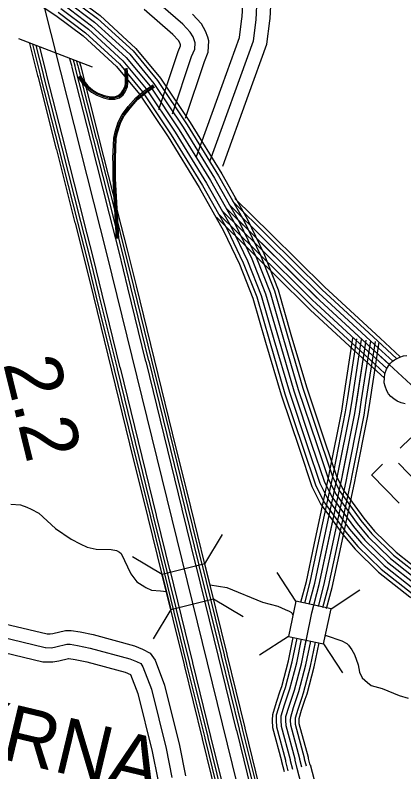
# Model space of a CAD drawing. Extents: x 1551132 to 1791609, y 378168 to 563823.
# Drawn here: x 1701091 to 1703654, y 427562 to 432556 of the extents above; entities that cross this region are included whole.
import ezdxf

# ---------------------------------------------------------------- set-up
doc = ezdxf.new("R2010")
doc.units = 0
for name, color, linetype in [('DESIGN - ROW - Right-of-Way and Easement Labels', 7, 'Continuous'), ('DESIGN - TRAFFIC CONTROL PERMANENT - Signalization', 7, 'Continuous'), ('DESIGN - TRANSPORTATION - Text', 7, 'Continuous'), ('DESIGN - UTILITIES - Cable (Underground) with Text', 7, 'Continuous'), ('SURVEY - CENTERLINE - Preliminary', 7, 'Continuous'), ('SURVEY - CENTERLINE - Preliminary Text', 7, 'Continuous'), ('SURVEY - DRAINAGE - Storm Sewer', 7, 'Continuous'), ('SURVEY - NON-TRANSPORTATION - Features Text', 7, 'Continuous'), ('SURVEY - PROPERTY - Owners', 7, 'Continuous'), ('SURVEY - TRANSPORTATION - Roads', 7, 'Continuous'), ('SURVEY - VEGETATION - Features with Text', 7, 'Continuous')]:
    doc.layers.add(name, color=color, linetype=linetype)

msp = doc.modelspace()

# ---------------------------------------------------------------- linework, layer by layer
at = {"layer": 'DESIGN - TRANSPORTATION - Text'}
for points in [[(1701061.398, 429329.616), (1701125.346, 429324.849), (1701167.17, 429308.332), (1701197.036, 429295.965), (1701246.743, 429269.348), (1701357.632, 429167.92), (1701460.872, 429098.619), (1701520.52, 429065.868), (1701566.294, 429045.301), (1701624.134, 429030.6), (1701724.14, 429029.417), (1701760.073, 429022.983), (1701777.956, 429012.758), (1701788.806, 429002.391)], [(1701788.806, 429002.391), (1701853.504, 428869.054), (1701892.645, 428815.361), (1701945.11, 428782.786), (1701952.11, 428777.994), (1701989.934, 428761.527), (1702049.891, 428756.81), (1702088.582, 428751.293)], [(1702376.4, 428795.261), (1702487.581, 428779.561), (1702722.384, 428681.183), (1702824.115, 428655.949), (1702871.872, 428633.357), (1702897.754, 428623.04), (1702913.646, 428612.84), (1702921.546, 428595.531)], [(1703136.815, 428462.853), (1703141.999, 428461.961), (1703245.613, 428426.693), (1703277.412, 428408.293), (1703289.303, 428398.143), (1703310.97, 428367.85), (1703328.611, 428335.608), (1703353.86, 428267.231), (1703361.318, 428219.088), (1703378.918, 428182.837), (1703414.584, 428152.378), (1703438.367, 428132.078), (1703510.165, 428113.202), (1703623.646, 428065.801), (1703681.469, 428049.1)]]:
    msp.add_lwpolyline(points, dxfattribs=at)
at = {"layer": 'DESIGN - UTILITIES - Cable (Underground) with Text'}
for p, q in [((1703700.78, 429767.058), (1703629.062, 429697.797)), ((1703513.294, 429591.71), (1703442.06, 429522.758)), ((1703441.618, 429522.366), (1703622.858, 429334.705))]:
    msp.add_line(p, q, dxfattribs=at)
msp.add_lwpolyline([(1703618.588, 429599.503), (1704009.76, 429194.514)], dxfattribs=at)
at = {"layer": 'SURVEY - CENTERLINE - Preliminary'}
for points in [[(1702996.559, 425884.268), (1702722.208, 426804.642), (1701697.609, 430973.251), (1701390.958, 432180.974), (1701199.605, 432943.303), (1700793.573, 434580.279), (1700461.64, 435904.33), (1700141.398, 437178.23), (1699727.417, 438823.273), (1699438.174, 439932.735), (1699182.397, 440953.853), (1698979.494, 441790.367), (1698870.455, 442275.771), (1698814.507, 442495.627)], [(1701240.928, 432156.549), (1701187.563, 432369.146)], [(1701257.903, 432160.807), (1701207.137, 432363.037)], [(1701277.302, 432165.674), (1701229.787, 432354.962)], [(1701296.744, 432171.499), (1701253.186, 432345.037)], [(1701465.923, 432213.967), (1701452.282, 432268.327)], [(1701485.598, 432218.909), (1701475.506, 432259.101)], [(1701589.12, 431728.663), (1701469.248, 432200.742), (1701466.148, 432213.084)], [(1701608.778, 431733.654), (1701488.914, 432205.708), (1701485.823, 432218.025)], [(1701504.997, 432223.776), (1701498.072, 432251.36)], [(1701628.161, 431738.58), (1701508.305, 432210.6), (1701505.222, 432222.892)], [(1701521.972, 432228.034), (1701518.272, 432242.768)], [(1701645.127, 431742.888), (1701525.272, 432214.884), (1701522.197, 432227.151)], [(1701364.267, 431670.628), (1701244.111, 432143.865), (1701241.162, 432155.607)], [(1701381.225, 431674.936), (1701261.078, 432148.157), (1701258.128, 432159.874)], [(1701400.616, 431679.853), (1701280.469, 432153.057), (1701277.527, 432164.749)], [(1701420.057, 431685.728), (1701300.127, 432158.04), (1701296.969, 432170.616)], [(1701712.392, 431243.142), (1701589.337, 431727.779)], [(1701732.05, 431248.133), (1701608.994, 431732.771)], [(1701751.433, 431253.059), (1701628.377, 431737.696)], [(1701768.399, 431257.359), (1701645.344, 431741.996)], [(1701487.547, 431185.115), (1701364.492, 431669.744)], [(1701504.513, 431189.415), (1701381.458, 431674.044)], [(1701523.896, 431194.34), (1701400.841, 431678.97)], [(1701543.329, 431200.207), (1701420.274, 431684.845)], [(1701890.129, 430770.371), (1701832.006, 431006.835), (1701768.624, 431256.484)], [(1701834.014, 430756.579), (1701775.948, 430992.827), (1701712.617, 431242.267)], [(1701853.713, 430761.421), (1701795.631, 430997.744), (1701732.275, 431247.258)], [(1701873.129, 430766.196), (1701815.031, 431002.594), (1701751.657, 431252.175)], [(1701608.727, 430700.269), (1701550.662, 430936.534), (1701487.772, 431184.232)], [(1701625.727, 430704.444), (1701567.637, 430940.775), (1701504.73, 431188.54)], [(1701645.143, 430709.219), (1701587.045, 430945.625), (1701524.121, 431193.457)], [(1701664.626, 430714.944), (1701606.719, 430950.542), (1701543.554, 431199.332)], [(1701953.577, 430270.141), (1701834.23, 430755.696)], [(1701973.277, 430274.983), (1701853.93, 430760.537)], [(1701992.693, 430279.758), (1701873.346, 430765.313)], [(1702009.684, 430283.933), (1701890.337, 430769.488)], [(1701764.707, 430222.782), (1701645.36, 430708.344)], [(1701784.19, 430228.507), (1701664.843, 430714.061)], [(1701728.291, 430213.823), (1701608.944, 430699.386)], [(1701745.291, 430218.006), (1701625.944, 430703.569)], [(1702073.141, 429783.695), (1701953.794, 430269.258)], [(1702092.841, 429788.537), (1701973.494, 430274.1)], [(1702112.257, 429793.312), (1701992.91, 430278.875)], [(1702129.248, 429797.487), (1702009.901, 430283.05)], [(1701847.855, 429727.377), (1701728.508, 430212.94)], [(1701864.854, 429731.56), (1701745.507, 430217.123)], [(1701884.27, 429736.336), (1701764.923, 430221.898)], [(1701903.753, 429742.061), (1701784.406, 430227.623)], [(1702192.705, 429297.257), (1702073.358, 429782.812)], [(1702212.404, 429302.099), (1702093.057, 429787.654)], [(1702231.82, 429306.874), (1702112.473, 429792.429)], [(1702248.812, 429311.05), (1702129.465, 429796.604)], [(1701967.418, 429240.939), (1701848.071, 429726.502)], [(1701984.418, 429245.123), (1701865.071, 429730.685)], [(1702003.834, 429249.898), (1701884.487, 429735.461)], [(1702023.317, 429255.623), (1701903.97, 429741.177)], [(1702324.451, 428929.99), (1702232.037, 429305.991)], [(1702341.743, 428932.948), (1702249.028, 429310.166)], [(1702285.369, 428920.239), (1702192.921, 429296.374)], [(1702305.052, 428925.156), (1702212.621, 429301.216)], [(1702060.049, 428864.054), (1701967.635, 429240.056)], [(1702077.04, 428868.288), (1701984.634, 429244.239)], [(1702154.597, 428636.515), (1702004.051, 429249.014)], [(1702116.123, 428878.021), (1702023.534, 429254.74)], [(1702431.824, 428324.374), (1702284.269, 428924.698)], [(1702451.523, 428329.216), (1702305.277, 428924.231)], [(1702470.939, 428333.991), (1702323.351, 428934.481)], [(1702487.939, 428338.166), (1702340.534, 428937.915)], [(1702206.537, 428268.064), (1702058.433, 428870.663)], [(1702223.537, 428272.239), (1702075.016, 428876.546)], [(1702262.436, 428282.739), (1702112.081, 428894.505)], [(1702242.953, 428277.014), (1702153.089, 428642.665)], [(1702551.387, 427837.928), (1702432.04, 428323.49)], [(1702571.087, 427842.77), (1702451.74, 428328.332)], [(1702590.503, 427847.545), (1702471.156, 428333.107)], [(1702607.494, 427851.72), (1702488.147, 428337.282)], [(1702326.101, 427781.609), (1702206.754, 428267.172)], [(1702343.1, 427785.793), (1702223.753, 428271.356)], [(1702362.517, 427790.568), (1702243.17, 428276.131)], [(1702381.999, 427796.293), (1702262.653, 428281.856)], [(1702670.951, 427351.49), (1702551.604, 427837.044)], [(1702690.65, 427356.332), (1702571.303, 427841.886)], [(1702710.067, 427361.107), (1702590.72, 427846.661)], [(1702727.058, 427365.282), (1702607.711, 427850.836)], [(1702445.664, 427295.172), (1702326.317, 427780.734)], [(1702462.664, 427299.355), (1702343.317, 427784.918)], [(1702482.08, 427304.13), (1702362.733, 427789.693)], [(1702501.563, 427309.856), (1702382.216, 427795.41)]]:
    msp.add_lwpolyline(points, dxfattribs=at)
at = {"layer": 'SURVEY - CENTERLINE - Preliminary Text'}
for points in [[(1701209.763, 432652.228), (1701359.142, 432553.751), (1701538.755, 432418.539), (1701759.974, 432215.675), (1701910.154, 432034.471), (1702098.975, 431751.98), (1702303.228, 431418.996), (1702465.316, 431131.347), (1702571.305, 430911.817), (1702659.186, 430687.844), (1702742.334, 430398.612), (1702844.765, 430049.611), (1702965.145, 429690.66), (1703047.685, 429445.92), (1703104.967, 429331.659), (1703251.713, 429128.287), (1703332.061, 429031.801), (1703487.766, 428880.23), (1703693.511, 428717.901), (1704065.744, 428504.096), (1704501.958, 428251.081), (1705242.932, 427815.937), (1705944.374, 427394.851), (1706600.392, 427005.216)], [(1701445.449, 432676.179), (1701634.594, 432533.792), (1701868.705, 432319.103), (1702030.343, 432124.082), (1702225.063, 431832.757), (1702432.292, 431494.924), (1702598.071, 431200.716), (1702708.602, 430971.802), (1702801.124, 430735.979), (1702886.106, 430440.379), (1702987.611, 430094.512), (1703107.05, 429738.394), (1703186.206, 429503.68), (1703233.414, 429409.519), (1703370.077, 429220.106), (1703442.092, 429133.629), (1703586.613, 428992.95), (1703777.609, 428842.255), (1704140.584, 428633.766), (1704577.423, 428380.393), (1705319.364, 427944.673), (1706021.122, 427523.404), (1706676.84, 427133.944)], [(1701459.698, 432696.388), (1701650.41, 432552.818), (1701886.663, 432336.179), (1702050.184, 432138.874), (1702245.88, 431846.091), (1702453.599, 431507.457), (1702619.995, 431212.166), (1702731.268, 430981.702), (1702824.557, 430743.921), (1702909.838, 430447.271), (1703011.194, 430101.929), (1703130.474, 429746.27), (1703209.073, 429513.214), (1703254.621, 429422.37), (1703389.618, 429235.265), (1703460.258, 429150.438), (1703602.93, 429011.559), (1703791.492, 428862.788), (1704152.942, 428655.175), (1704589.881, 428401.735), (1705331.989, 427965.932), (1706033.797, 427544.63), (1706689.465, 427155.195)], [(1701409.708, 432625.478), (1701594.903, 432486.066), (1701823.681, 432276.269), (1701980.569, 432086.972), (1702172.848, 431799.306), (1702378.843, 431463.481), (1702543.097, 431171.99), (1702651.745, 430946.959), (1702742.342, 430716.045), (1702826.565, 430423.079), (1702928.454, 430075.92), (1703048.285, 429718.627), (1703128.841, 429479.763), (1703180.223, 429377.277), (1703321.061, 429182.08), (1703396.526, 429091.461), (1703545.681, 428946.274), (1703742.785, 428790.762), (1704109.593, 428580.065), (1704546.174, 428326.841), (1705287.715, 427891.364), (1705989.34, 427470.17), (1706645.183, 427080.635)], [(1701409.708, 432625.478), (1701594.903, 432486.066), (1701823.681, 432276.269), (1701980.569, 432086.972), (1702172.848, 431799.306), (1702378.843, 431463.481), (1702543.097, 431171.99), (1702651.745, 430946.959), (1702742.342, 430716.045), (1702826.565, 430423.079), (1702928.454, 430075.92), (1703048.285, 429718.627), (1703128.841, 429479.763), (1703180.223, 429377.277), (1703321.061, 429182.08), (1703396.526, 429091.461), (1703545.681, 428946.274), (1703742.785, 428790.762), (1704109.593, 428580.065), (1704546.174, 428326.841), (1705287.715, 427891.364), (1705989.34, 427470.17), (1706645.183, 427080.635)], [(1701427.574, 432650.828), (1701614.745, 432509.933), (1701846.197, 432297.686), (1702005.452, 432105.523), (1702198.956, 431816.032), (1702405.567, 431479.198), (1702570.588, 431186.357), (1702680.169, 430959.376), (1702771.733, 430726.012), (1702856.331, 430431.729), (1702958.029, 430085.22), (1703077.667, 429728.511), (1703157.524, 429491.721), (1703206.823, 429393.394), (1703345.569, 429201.089), (1703419.309, 429112.545), (1703566.147, 428969.616), (1703760.201, 428816.512), (1704125.092, 428606.915), (1704561.799, 428353.617), (1705303.539, 427918.023), (1706005.231, 427496.787), (1706661.016, 427107.285)], [(1701373.967, 432574.776), (1701555.213, 432438.34), (1701778.657, 432233.434), (1701930.795, 432049.863), (1702120.632, 431765.856), (1702325.394, 431432.039), (1702488.124, 431143.264), (1702594.888, 430922.117), (1702683.56, 430696.111), (1702767.025, 430405.778), (1702869.297, 430057.328), (1702989.519, 429698.86), (1703071.476, 429455.845), (1703127.033, 429345.034), (1703272.046, 429144.054), (1703350.961, 429049.293), (1703504.749, 428899.598), (1703707.961, 428739.269), (1704078.602, 428526.363), (1704514.925, 428273.29), (1705256.065, 427838.054), (1705957.557, 427416.935), (1706613.525, 427027.325)], [(1701391.842, 432600.127), (1701575.062, 432462.199), (1701801.165, 432254.852), (1701955.686, 432068.422), (1702146.74, 431782.581), (1702352.119, 431447.764), (1702515.606, 431157.623), (1702623.32, 430934.542), (1702712.951, 430706.078), (1702796.799, 430414.429), (1702898.88, 430066.62), (1703018.902, 429708.744), (1703100.158, 429467.804), (1703153.624, 429361.16), (1703296.554, 429163.071), (1703373.743, 429070.377), (1703525.215, 428922.932), (1703725.368, 428765.011), (1704094.093, 428553.214), (1704530.549, 428300.066), (1705271.89, 427864.705), (1705973.448, 427443.552), (1706629.35, 427053.984)]]:
    msp.add_lwpolyline(points, dxfattribs=at)
at = {"layer": 'SURVEY - DRAINAGE - Storm Sewer'}
for p, q in [((1701600.878, 432211.675), (1701114.881, 432398.205)), ((1702341.384, 428934.215), (1702458.382, 429128.903)), ((1702059.924, 428864.021), (1701865.245, 428981.007)), ((1702941.814, 428687.986), (1702818.101, 428878.475)), ((1703174.224, 428638.592), (1703364.713, 428762.305)), ((1702398.808, 428703.95), (1702593.495, 428586.981)), ((1702117.348, 428633.757), (1702000.375, 428439.06)), ((1702892.42, 428455.576), (1702701.939, 428331.879)), ((1703124.78, 428406.19), (1703248.476, 428215.718))]:
    msp.add_line(p, q, dxfattribs=at)
for points in [[(1702117.348, 428633.757), (1702398.808, 428703.95), (1702341.384, 428934.215), (1702059.924, 428864.021)], [(1702892.42, 428455.576), (1703124.83, 428406.182), (1703174.224, 428638.592), (1702941.814, 428687.986)]]:
    msp.add_lwpolyline(points, close=True, dxfattribs=at)
at = {"layer": 'SURVEY - NON-TRANSPORTATION - Features Text'}
for points in [[(1701505.714, 432148.915), (1701521.047, 432122.981), (1701559.779, 432077.505), (1701594.745, 432048.304), (1701629.894, 432027.295), (1701673.068, 432010.503), (1701708.576, 432001.895), (1701747.791, 432001.203), (1701778.091, 432010.362), (1701802.623, 432030.196), (1701815.931, 432049.921), (1701831.031, 432083.889), (1701833.356, 432105.756), (1701833.531, 432134.24), (1701833.614, 432148.615), (1701829.581, 432204.684)], [(1701513.463, 432153.499), (1701528.396, 432128.231), (1701566.137, 432083.922), (1701599.97, 432055.663), (1701633.861, 432035.412), (1701675.768, 432019.112), (1701709.725, 432010.878), (1701746.541, 432010.228), (1701773.799, 432018.47), (1701795.915, 432036.346), (1701808.032, 432054.296), (1701822.231, 432086.247), (1701824.356, 432106.264), (1701824.531, 432134.298), (1701824.615, 432148.315), (1701820.606, 432204.042)], [(1701519.488, 432157.057), (1701534.113, 432132.315), (1701571.079, 432088.914), (1701604.036, 432061.388), (1701636.944, 432041.721), (1701677.868, 432025.804), (1701710.625, 432017.862), (1701745.566, 432017.245), (1701770.466, 432024.779), (1701790.699, 432041.129), (1701801.882, 432057.705), (1701815.39, 432088.08), (1701817.356, 432106.656), (1701817.531, 432134.34), (1701817.615, 432148.082), (1701813.623, 432203.542)], [(1701767.19, 431082.321), (1701746.074, 431475.131), (1701744.908, 431609.335), (1701750.341, 431742.696), (1701757.983, 431783.489), (1701778.374, 431845.449), (1701804.69, 431895.342), (1701843.022, 431947.168), (1701893.38, 432002.92), (1701949.695, 432050.613), (1702005.152, 432088.997)], [(1701915.179, 432033.179), (1701944.212, 432057.763), (1702000.027, 432096.397)], [(1701925.52, 432020.97), (1701953.961, 432045.054), (1702009.135, 432083.239)], [(1701736.15, 431581.659), (1701735.908, 431609.476), (1701741.375, 431743.713), (1701749.249, 431785.731), (1701770.057, 431848.983), (1701797.048, 431900.142), (1701836.048, 431952.877), (1701887.105, 432009.403), (1701915.196, 432033.187)], [(1701752.149, 431581.792), (1701751.908, 431609.226), (1701757.316, 431741.905), (1701764.774, 431781.739), (1701784.84, 431842.699), (1701810.631, 431891.609), (1701848.447, 431942.727), (1701898.263, 431997.878), (1701925.537, 432020.979)], [(1701758.207, 431081.837), (1701737.075, 431474.848), (1701736.15, 431581.676)], [(1701774.182, 431082.696), (1701753.074, 431475.348), (1701752.149, 431581.809)]]:
    msp.add_lwpolyline(points, dxfattribs=at)
at = {"layer": 'SURVEY - PROPERTY - Owners'}
for points in [[(1702128.207, 431903.751), (1702254.138, 432281.919), (1702274.696, 432331.729), (1702277.171, 432373.747), (1702263.596, 432411.956), (1702245.955, 432444.207), (1702196.539, 432496.858), (1702002.402, 432665.379), (1701903.263, 432742.656), (1701812.157, 432823.85), (1701776.633, 432866.318), (1701753.058, 432904.652), (1701731.434, 432938.944), (1701715.867, 432977.179), (1701694.968, 433075.54), (1701612.712, 433410.915), (1701407.575, 434204.294), (1701114.416, 435353.141), (1700809.474, 436522.155), (1700675.51, 437062.385), (1700654.344, 437136.729), (1700646.819, 437178.863), (1700706.402, 437676.726)], [(1702286.512, 431621.818), (1702456.408, 432092.073), (1702570.422, 432407.656), (1702586.264, 432533.851), (1702586.772, 432543.376), (1702593.672, 432672.563)], [(1702375.193, 431589.776), (1702662.67, 432385.489), (1702680.236, 432525.442), (1702687.828, 432667.513)], [(1702460.499, 431558.95), (1702630.396, 432029.204), (1702751.41, 432364.163), (1702770.643, 432517.35), (1702771.501, 432533.484), (1702778.401, 432662.654)], [(1702038.751, 431933.543), (1702165.723, 432314.845), (1702181.498, 432353.071), (1702181.923, 432360.196), (1702177.265, 432373.305), (1702168.99, 432388.422), (1702131.091, 432428.806), (1701942.479, 432592.535)], [(1702214.264, 431875.092), (1702339.194, 432250.243), (1702364.352, 432311.195), (1702368.802, 432386.814), (1702360.81, 432409.264), (1702346.652, 432449.14), (1702319.995, 432497.866), (1702259.505, 432562.318)], [(1700937.375, 428559.513), (1701301.017, 428472.469), (1701321.883, 428472.327), (1701339.774, 428475.869), (1701421.981, 428495.294), (1701460.971, 428495.011), (1701519.553, 428485.086), (1701605.443, 428467.469), (1701877.012, 428394.742), (1701929.66, 428372.616), (1701980.992, 428346.299), (1702013.9, 428298.323), (1702076.348, 428134.452), (1702174.663, 427735.975), (1702214.495, 427535.786)], [(1700913.951, 428471.844), (1701289.242, 428382.016), (1701291.075, 428381.825), (1701330.466, 428381.558), (1701359.015, 428387.208), (1701432.23, 428404.509), (1701453.013, 428404.359), (1701502.862, 428395.909), (1701584.585, 428379.15), (1701847.571, 428308.723), (1701891.345, 428290.323), (1701919.177, 428276.056), (1701932.985, 428255.922), (1701989.617, 428107.335), (1702086.106, 427716.249), (1702124.397, 427523.803)], [(1700889.601, 428380.716), (1701273.301, 428288.872), (1701285.842, 428287.564), (1701339.391, 428287.197), (1701379.015, 428295.048), (1701442.88, 428310.131), (1701444.738, 428310.123), (1701485.504, 428303.214), (1701562.902, 428287.339), (1701816.963, 428219.304), (1701851.512, 428204.779), (1701851.587, 428204.745), (1701899.453, 428079.142), (1701994.05, 427695.74), (1702030.741, 427511.344)], [(1703355.168, 426211.044), (1703154.273, 426799.859), (1702951.544, 427584.771)], [(1703441.016, 426240.336), (1703279.561, 426713.557), (1703241.237, 426825.885), (1703147.598, 427188.403), (1703039.367, 427607.455)]]:
    msp.add_lwpolyline(points, dxfattribs=at)
at = {"layer": 'SURVEY - TRANSPORTATION - Roads'}
for points in [[(1702738.168, 431073.038), (1702501.332, 431306.819)], [(1702759.942, 431095.097), (1702523.106, 431328.878)], [(1702777.308, 431112.689), (1702540.472, 431346.47)], [(1702694.619, 431028.903), (1702457.783, 431262.684)], [(1703757.718, 430065.42), (1703099.001, 430673.311), (1702479.557, 431284.751)], [(1702716.393, 431050.97), (1702479.557, 431284.751)], [(1702654.778, 430988.544), (1702417.942, 431222.325)], [(1702672.844, 431006.844), (1702436.008, 431240.625)], [(1703133.142, 430761.455), (1702777.3, 431112.705)], [(1703094.001, 430721.804), (1702738.159, 431073.054)], [(1703115.775, 430743.863), (1702759.934, 431095.113)], [(1703028.677, 430655.61), (1702672.836, 431006.861)], [(1703050.452, 430677.669), (1702694.61, 431028.92)], [(1703072.226, 430699.736), (1702716.385, 431050.987)], [(1703010.611, 430637.31), (1702654.77, 430988.56)], [(1703497.591, 430423.471), (1703158.883, 430736.046), (1703133.142, 430761.463)], [(1703459.809, 430382.528), (1703120.408, 430695.736), (1703093.992, 430721.812)], [(1703480.833, 430405.312), (1703141.816, 430718.17), (1703115.775, 430743.879)], [(1703396.735, 430314.176), (1703056.185, 430628.451), (1703028.661, 430655.627)], [(1703417.76, 430336.96), (1703077.593, 430650.885), (1703050.443, 430677.694)], [(1703438.784, 430359.744), (1703099.001, 430673.311), (1703072.218, 430699.753)], [(1703379.302, 430295.276), (1703038.427, 430609.851), (1703010.594, 430637.326)], [(1702951.544, 427584.771), (1702937.578, 427638.839), (1702937.645, 427644.839), (1702878.096, 427865.654), (1702876.513, 427903.696), (1702876.771, 427927.714), (1702897.479, 427995.515), (1702932.587, 428101.176), (1702978.419, 428274.756), (1703047.993, 428612.165), (1703096.617, 428799.087), (1703245.53, 429496.013), (1703330.628, 429926.933), (1703405.093, 430411.054)], [(1703258.53, 430035.169), (1703318.395, 430424.388)], [(1703283.946, 430031.261), (1703343.811, 430420.479)], [(1703314.587, 430026.552), (1703374.452, 430415.771)], [(1703345.228, 430021.835), (1703405.093, 430411.054)], [(1703375.869, 430017.119), (1703435.734, 430406.337)], [(1703606.247, 430289.576), (1703480.825, 430405.32)], [(1703630.205, 430301.093), (1703497.583, 430423.479)], [(1703406.51, 430012.41), (1703466.375, 430401.629)], [(1703430.934, 430008.652), (1703490.8, 430397.87)], [(1703558.598, 430249.175), (1703438.776, 430359.753)], [(1703580.381, 430271.259), (1703459.8, 430382.537)], [(1703529.415, 430191.74), (1703396.727, 430314.185)], [(1703541.432, 430222.832), (1703417.751, 430336.969)], [(1703525.882, 430160.006), (1703379.294, 430295.284)], [(1703166.307, 429547.598), (1703244.214, 429942.108), (1703258.53, 430035.186)], [(1703191.54, 429542.614), (1703269.546, 429937.658), (1703283.946, 430031.277)], [(1703221.947, 429536.614), (1703300.087, 429932.291), (1703314.587, 430026.569)], [(1703252.363, 429530.606), (1703330.628, 429926.933), (1703345.228, 430021.852)], [(1703282.779, 429524.597), (1703361.169, 429921.574), (1703375.869, 430017.135)], [(1703313.187, 429518.597), (1703391.71, 429916.208), (1703406.51, 430012.427)], [(1703337.436, 429513.805), (1703416.06, 429911.932), (1703430.934, 430008.668)], [(1703062.642, 429059.86), (1703159.607, 429513.672), (1703166.307, 429547.614)], [(1703087.792, 429054.493), (1703184.798, 429508.497), (1703191.54, 429542.631)], [(1703118.108, 429048.01), (1703215.164, 429502.255), (1703221.947, 429536.631)], [(1703148.424, 429041.535), (1703245.53, 429496.013), (1703252.363, 429530.622)], [(1703178.74, 429035.059), (1703275.896, 429489.771), (1703282.779, 429524.614)], [(1703209.056, 429028.576), (1703306.262, 429483.53), (1703313.187, 429518.614)], [(1703233.222, 429023.417), (1703330.47, 429478.554), (1703337.436, 429513.822)], [(1702975.611, 428682.342), (1703011.244, 428819.304), (1703062.642, 429059.885)], [(1703000.569, 428676.133), (1703036.268, 428813.379), (1703087.792, 429054.51)], [(1703030.66, 428668.666), (1703066.442, 428806.228), (1703118.108, 429048.026)], [(1703060.726, 428661.108), (1703096.617, 428799.087), (1703148.424, 429041.551)], [(1703090.817, 428653.649), (1703126.791, 428791.945), (1703178.74, 429035.076)], [(1703120.874, 428646.083), (1703156.965, 428784.794), (1703209.056, 429028.593)], [(1703144.882, 428640.182), (1703181.015, 428779.103), (1703233.222, 429023.434)], [(1702838.347, 428095.726), (1702848.48, 428126.227), (1702892.996, 428294.823), (1702924.729, 428448.711)], [(1702862.747, 428087.618), (1702873.138, 428118.885), (1702918.037, 428288.94), (1702949.87, 428443.344)], [(1702892.171, 428077.843), (1702902.862, 428110.027), (1702948.228, 428281.848), (1702980.211, 428436.935)], [(1702921.587, 428068.067), (1702932.587, 428101.176), (1702978.419, 428274.756), (1703010.527, 428430.468)], [(1702951.003, 428058.292), (1702962.311, 428092.326), (1703008.61, 428267.664), (1703040.851, 428424.043)], [(1702980.427, 428048.517), (1702992.035, 428083.468), (1703038.801, 428260.572), (1703071.175, 428417.593)], [(1703003.877, 428040.725), (1703015.735, 428076.409), (1703062.867, 428254.914), (1703095.358, 428412.46)], [(1702866.621, 427562.829), (1702849.738, 427628.172), (1702849.797, 427633.697), (1702790.865, 427852.245), (1702788.782, 427902.346), (1702789.198, 427941.272), (1702813.906, 428022.166), (1702838.356, 428095.751)], [(1702891.512, 427569.262), (1702875.488, 427631.297), (1702875.555, 427636.964), (1702816.439, 427856.178), (1702814.498, 427902.738), (1702814.873, 427937.297), (1702838.406, 428014.349), (1702862.763, 428087.634)], [(1702921.528, 427577.021), (1702906.537, 427635.073), (1702906.604, 427640.898), (1702847.264, 427860.912), (1702845.505, 427903.221), (1702845.822, 427932.505), (1702867.947, 428004.932), (1702892.179, 428077.859)], [(1702951.544, 427584.771), (1702937.578, 427638.839), (1702937.645, 427644.839), (1702878.096, 427865.654), (1702876.513, 427903.696), (1702876.771, 427927.714), (1702897.479, 427995.515), (1702921.595, 428068.084)], [(1702981.56, 427592.521), (1702968.619, 427642.606), (1702968.686, 427648.781), (1702908.929, 427870.395), (1702907.521, 427904.171), (1702907.721, 427922.922), (1702927.012, 427986.098), (1702951.011, 428058.309)], [(1703011.576, 427600.28), (1702999.668, 427646.381), (1702999.735, 427652.715), (1702939.753, 427875.129), (1702938.528, 427904.655), (1702938.67, 427918.13), (1702956.553, 427976.682), (1702980.427, 428048.533)], [(1703035.501, 427606.464), (1703024.418, 427649.381), (1703024.484, 427655.856), (1702964.336, 427878.912), (1702963.244, 427905.038), (1702963.344, 427914.313), (1702980.102, 427969.173), (1703003.885, 428040.733)]]:
    msp.add_lwpolyline(points, dxfattribs=at)
at = {"layer": 'SURVEY - VEGETATION - Features with Text'}
msp.add_lwpolyline([(1703663.679, 429991.143), (1703635.388, 429998.068), (1703610.588, 430008.977), (1703587.347, 430023.085), (1703568.206, 430039.778), (1703553.473, 430056.453), (1703541.39, 430077.479), (1703531.107, 430108.263), (1703525.265, 430129.947), (1703526.032, 430163.256), (1703528.532, 430189.581), (1703540.082, 430220.307), (1703552.306, 430241.366), (1703566.39, 430258.708), (1703577.839, 430268.959), (1703592.531, 430281.259), (1703609.247, 430290.801), (1703627.871, 430299.618), (1703651.471, 430307.335), (1703673.837, 430309.985)], dxfattribs=at)

# ---------------------------------------------------------------- texts
at = {"layer": 'DESIGN - ROW - Right-of-Way and Easement Labels'}
msp.add_text('SMYRNA', height=369.9922, rotation=346.538711, dxfattribs=at).set_placement((1699943.336, 427900.813))
at = {"layer": 'DESIGN - TRAFFIC CONTROL PERMANENT - Signalization'}
msp.add_text('2.2', height=370.0086, rotation=283.809053, dxfattribs=at).set_placement((1701010.107, 430257.495))

doc.saveas('drawing.dxf')
